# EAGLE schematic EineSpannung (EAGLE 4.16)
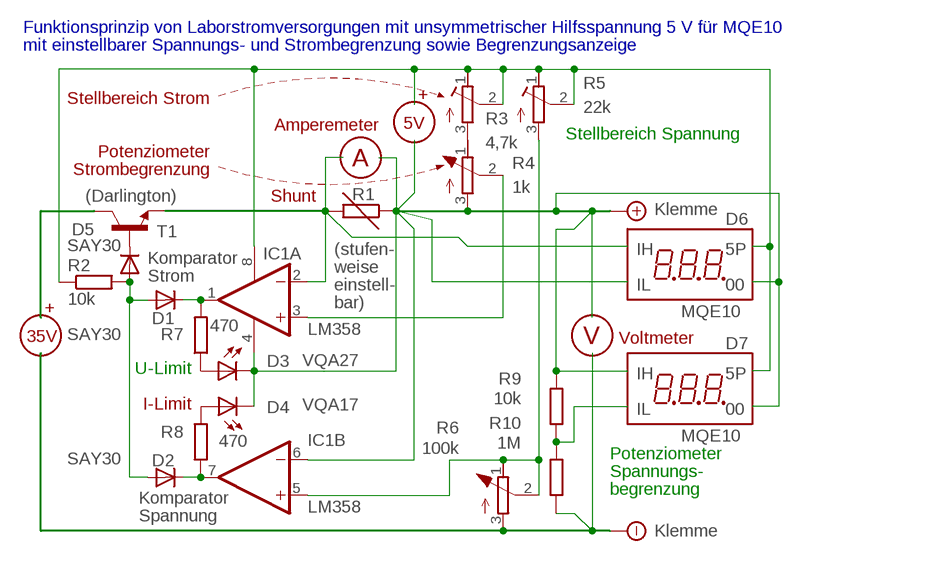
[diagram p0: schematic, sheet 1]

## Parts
D1  SAY30  DIODE-D-10  [D-10]
D2  SAY30  DIODE-D-10  [D-10]
D3  VQA27  LED5MM  [LED5MM]
D4  VQA17  LED5MM  [LED5MM]
D5  SAY30  DIODE-D-10  [D-10]
IC1  LM358  TL082P  [DIL08]
R1  R-EU_0207/10  [0207/10]
R2  10k  R-EU_0207/10  [0207/10]
R3  4,7k  R-TRIMMT93YB  [RTRIMT93YB]
R4  1k  R-TRIMMT93YB  [RTRIMT93YB]
R5  22k  R-TRIMMT93YB  [RTRIMT93YB]
R6  100k  R-TRIMMT93YB  [RTRIMT93YB]
R7  470  R-EU_0207/10  [0207/10]
R8  470  R-EU_0207/10  [0207/10]
R9  10k  R-EU_0207/10  [0207/10]
R10  1M  R-EU_0207/10  [0207/10]
T1  -NPN-TO3/  [TO3]

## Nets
00: D3.K(C) D4.K(C) IC1.4(P:V-) IC1.6(B:-IN) R1.1 R4.3(E) R9.2 ; supply symbol labelled Klemme
5P: IC1.8(P:V+) R2.1 R3.1(A) R3.2(S) R5.1(A) R5.2(S)
+UB: T1.C
-UB: R6.3(E) R10.1 ; supply symbol labelled Klemme
N$1: D1.A D2.A D5.A R2.2
N$2: IC1.3(A:+IN) R4.2(S)
N$3: D3.A R7.1
N$4: D4.A R8.2
N$5: R9.1 R10.2
N$6: R3.3(E) R4.1(A)
N$7: D5.C T1.B
N$8: D2.C IC1.7(B:OUT) R8.1
N$9: D1.C IC1.1(A:OUT) R7.2
N$15: IC1.2(A:-IN) R1.2 T1.E
N$85: IC1.5(B:+IN) R5.3(E) R6.1(A) R6.2(S)

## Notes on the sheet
- Funktionsprinzip von Laborstromversorgungen mit unsymmetrischer Hilfsspannung 5 V für MQE10
- mit einstellbarer Spannungs- und Strombegrenzung sowie Begrenzungsanzeige
- Stellbereich Strom | +
- Amperemeter | 5V
- Stellbereich Spannung
- Potenziometer
- A
- Strombegrenzung
- (Darlington) | Shunt
- D6
- (stufen- | IH | 5P
- Komparator
- weise
- Strom
- einstell- | IL | 00
- bar)
- + | MQE10
- 35V | V | Voltmeter
- D7
- U-Limit
- IH | 5P
- I-Limit
- IL | 00
- MQE10
- Potenziometer
- Spannungs-
- begrenzung
- Komparator
- Spannung

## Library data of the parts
D1 D2 D5 = diode:DIODE-: DIODE
D3 D4 = led:LED: LED
IC1 = linear:TL082: OP AMP
R1 R2 R7-R10 = rcl:R-EU_: RESISTOR, European symbol
R3-R6 = rcl:R-TRIMM: Trimm resistor
T1 = transistor:*-NPN-: NPN Transistror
